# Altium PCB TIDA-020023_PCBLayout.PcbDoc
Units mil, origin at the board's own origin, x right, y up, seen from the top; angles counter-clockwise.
Board outline 1062.99 x 787.4 mil, 2 copper layers (Top Layer, Bottom Layer), stack 62 mil thick; 38 components, 20 nets, 86 pads, 14 vias.
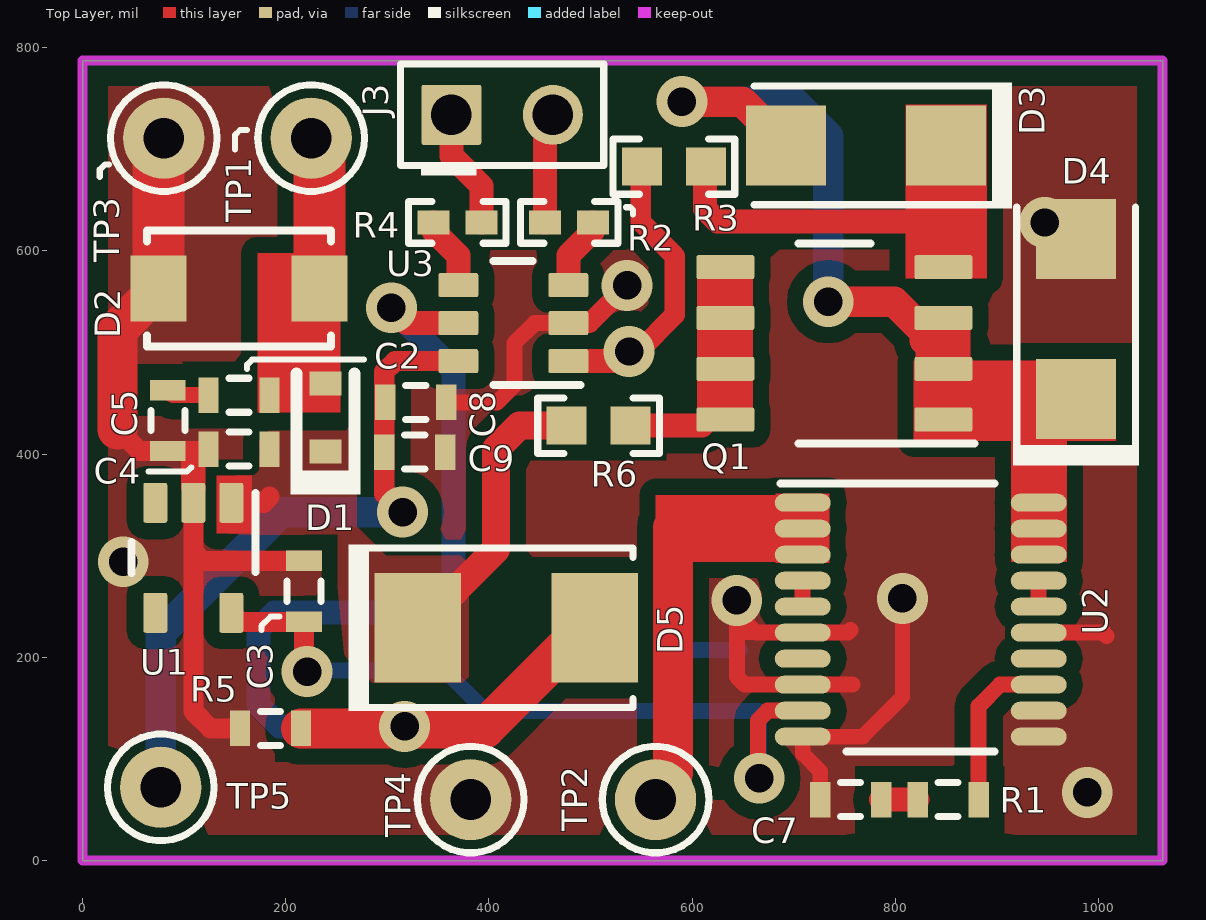
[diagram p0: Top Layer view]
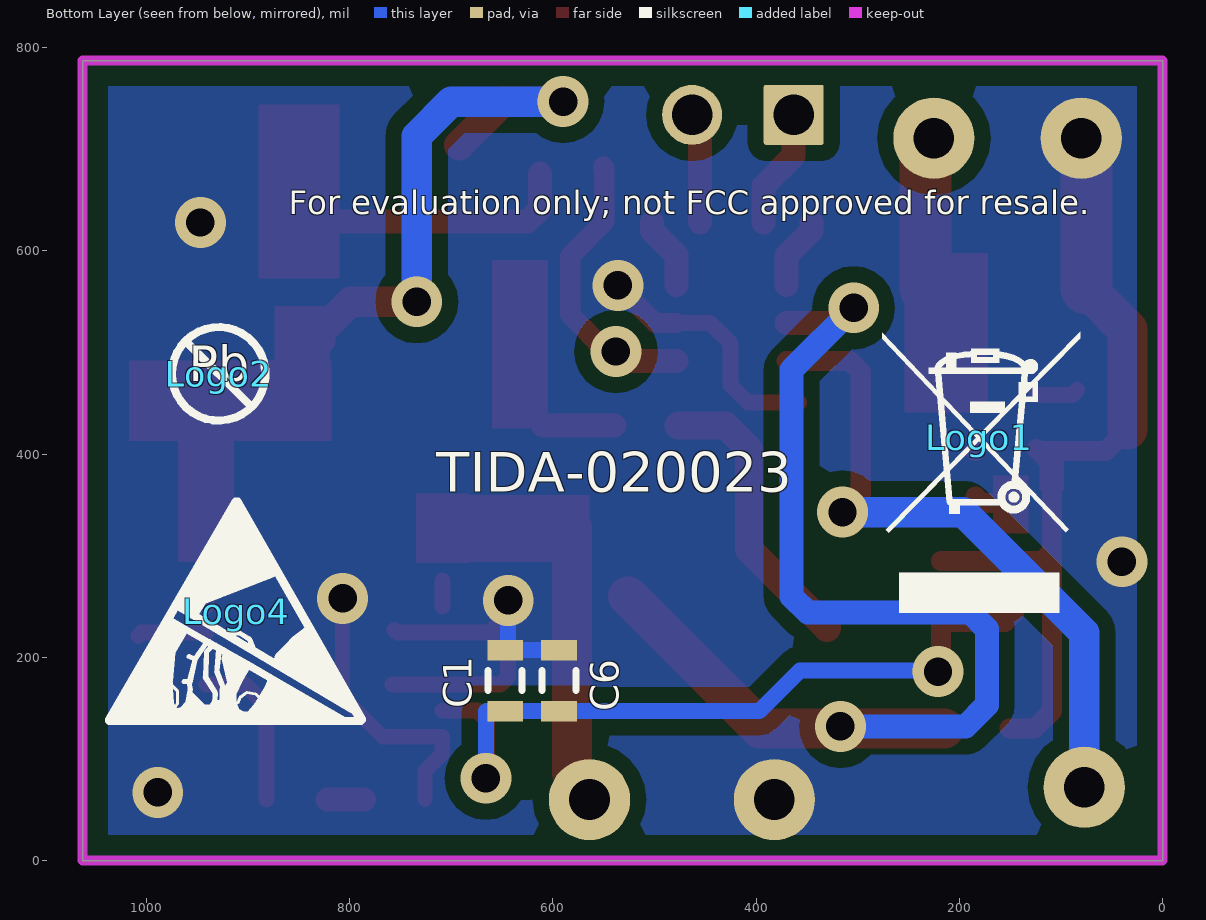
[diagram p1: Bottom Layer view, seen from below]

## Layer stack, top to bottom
Top Solder: solder mask 0.4, Solder Resist, Dk 3.5
Top Layer: signal copper 1.4
Dielectric1: core 59.2, FR-4, Dk 4.8
Bottom Layer: signal copper 1.4
Bottom Solder: solder mask 0.4, Solder Resist, Dk 3.5

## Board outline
0,0 1062.99,0 1062.99,787.4 0,787.4

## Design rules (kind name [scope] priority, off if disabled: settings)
AcuteAngle [All] p1: minimum=4.50000000000000E+0001 checktracksonly=FALSE
AssemblyTestPointUsage [All] p1: valid=2
BoardOutlineClearance BoardOutlineClearance_MountingHoles [OnCopper and InComponentClass('Mounting Holes')] p1: gap=40 ignorepadtopadclearanceinfootprint=FALSE
BoardOutlineClearance BoardOutlineClearance_Poly [OnCopper and IsPoly] p2: gap=25 ignorepadtopadclearanceinfootprint=FALSE
BoardOutlineClearance [OnCopper and Not InComponentClass('Logo') and not InComponentClass('FiducialMark') and not InRegion(1000,500,4000,800) and not InPoly] p3: gap=0 ignorepadtopadclearanceinfootprint=FALSE
Clearance Clearance_Keepouts [((IsTrack Or IsArc) And Not InPoly) And IsFree and IsKeepOut vs ((IsTrack Or IsArc) And Not InPoly) And IsFree and IsKeepOut] p1: gap=0 ignorepadtopadclearanceinfootprint=FALSE
Clearance Clearance_Poly [InPolygon] p2: gap=15.75 ignorepadtopadclearanceinfootprint=FALSE except(0: Arc-Hole Track-Hole SMDPad-Hole THPad-Hole Via-Hole Fill-Hole Poly-Hole Region-Hole Text-Hole)
Clearance [All] p3: gap=7.87 ignorepadtopadclearanceinfootprint=FALSE except(0: Arc-Hole Track-Hole SMDPad-Hole THPad-Hole Via-Hole Fill-Hole Poly-Hole Region-Hole Text-Hole)
ComponentClearance ComponentClearance_MountingHoles_FiducialMarks [InComponentClass('Mounting Holes') vs InComponentClass('FiducialMark')] p1: gap=50 collisioncheckmode=3 verticalgap=10 showdistances=FALSE
ComponentClearance ComponentClearance_Shunt [InComponentClass('Header') vs InComponentClass('Shunt')] p2: gap=0 collisioncheckmode=3 verticalgap=0 showdistances=FALSE
ComponentClearance ComponentClearance_Logo [InComponentClass('Logo')] p3: gap=0 collisioncheckmode=3 verticalgap=10 showdistances=FALSE
ComponentClearance ComponentClearance_ScrewToNut [(HasFootprint('NY PMS 440 0025 PH')) vs (HasFootprint('Keystone_1902C'))] p4: gap=5 collisioncheckmode=3 verticalgap=0 showdistances=FALSE
ComponentClearance ComponentClearance_MountingHoles [InComponentClass('Mounting Holes')] p5: gap=0 collisioncheckmode=3 verticalgap=100000 showdistances=FALSE
ComponentClearance ComponentClearance_SmallPassives [HasFootprint('0201*') or HasFootprint('0402*') or HasFootprint('0508') or HasFootprint('0603*') or HasFootprint('0612') or HasFootprint('0805*') or HasFootprint('0815*') or HasFootprint('0830*') or HasFootprint('1206*') or HasFootprint('1210*') or HasFootprint('1808*') or HasFootprint('1812*') or HasFootprint('1825*') or HasFootprint('2010*') or HasFootprint('2220*') or HasFootprint('2225*') or HasFootprint('2512*') or HasFootprint('2728*') or HasFootprint('3518*') vs HasFootprint('0201*') or HasFootprint('0402*') or HasFootprint('0508') or HasFootprint('0603*') or HasFootprint('0612') or HasFootprint('0805*') or HasFootprint('0815*') or HasFootprint('0830*') or HasFootprint('1206*') or HasFootprint('1210*') or HasFootprint('1808*') or HasFootprint('1812*') or HasFootprint('1825*') or HasFootprint('2010*') or HasFootprint('2220*') or HasFootprint('2225*') or HasFootprint('2512*') or HasFootprint('2728*') or HasFootprint('3518*')] p6: gap=0 collisioncheckmode=3 verticalgap=0 showdistances=FALSE
ComponentClearance ComponentClearance_THtoSMT [IsThruComponent vs IsSMTComponent] p7: gap=0 collisioncheckmode=3 verticalgap=0 showdistances=FALSE
ComponentClearance ComponentClearance_THtoTH [IsThruComponent vs IsThruComponent] p8: gap=0 collisioncheckmode=3 verticalgap=0 showdistances=FALSE
ComponentClearance [All] p9: gap=0 collisioncheckmode=3 verticalgap=0 showdistances=FALSE
DiffPairsRouting [All] p1: maxlimit=100 minlimit=10 mostfreqgap=10 toplayer_minwidth=15 toplayer_maxwidth=15 toplayer_prefwidth=15 bottomlayer_minwidth=15 bottomlayer_maxwidth=15 bottomlayer_prefwidth=15 maxuncoupledlength=1000
FabricationTestPointUsage TestPointUsage [All] p1: valid=2 allowmultiple=FALSE
FabricationTestpoint Testpoint [All] p1: side=3 testpointundercomponent=TRUE minsize=40 maxsize=100 preferedsize=60 minholesize=0 maxholesize=40 preferedholesize=32 testpointgrid=1 allowsidetop=TRUE allowsidebottom=TRUE usegrid=TRUE gridtolerance=0.01
FanoutControl Fanout_LCC [IsLCC] p1: bgadir=Out bgaviamode=Centered fanoutstyle=Auto fanoutdirection=Alternating viagrid=1 // Fanout_LCC (Default Rule)
FanoutControl Fanout_BGA [IsBGA] p2: bgadir=Out bgaviamode=Centered fanoutstyle=Auto fanoutdirection=Alternating viagrid=1 // Fanout_BGA (Default Rule)
FanoutControl Fanout_Default [All] p4: bgadir=Out bgaviamode=Centered fanoutstyle=Auto fanoutdirection=Alternating viagrid=1 // Fanout_Default (Default Rule)
FanoutControl Fanout_Small [(CompPinCount < 5)] p5: bgadir=Out bgaviamode=Centered fanoutstyle=Auto fanoutdirection=OutThenIn viagrid=1 // Fanout_Small (Default Rule)
HoleSize [All] p1: absolutevalues=TRUE maxlimit=251 minlimit=7.87 maxpercent=80.000 minpercent=20.000
MinimumAnnularRing MinimumAnnularRing_ThermalPadVias [IsVia and InAnyComponent] p1: minimumring=0
MinimumAnnularRing [All] p2: minimumring=0
MinimumSolderMaskSliver MinimumSolderMaskSliver_Logo [InComponentClass('Logo') vs InComponentClass('Logo')] p1: minsoldermaskwidth=0.7
MinimumSolderMaskSliver [All] p2: minsoldermaskwidth=3.94
PlaneConnect [All] p1: planeconnectstyle=Relief reliefexpansion=10 reliefentries=4 reliefconductorwidth=10 reliefairgap=10
PolygonConnect [All] p1: connectstyle=Direct reliefconductorwidth=10 reliefentries=4 polygonreliefangle="90 Angle" airgapwidth=10
RoutingVias ThermalPadVias [IsVia and InAnyComponent] p1: holewidth=7.87 width=19.68 viastyle="Through Hole" minholewidth=7.87 minwidth=19.68 maxholewidth=12.99 maxwidth=23.62
RoutingVias [All] p2: holewidth=16 width=34 viastyle="Through Hole" minholewidth=7.87 minwidth=26 maxholewidth=40 maxwidth=65
SilkToBoardRegionClearance [Not ((IsComment or IsDesignator) And (Hide <> 'False')) and not InRegion(1000,500,4000,800)] p1:
SilkToSilkClearance SilkToSilkClearance_Pb-FreeLogo [(HasFootprint('Pb-Free_Overlay_Medium') OR HasFootprint('Pb-Free_Overlay_Small')) vs (HasFootprint('Pb-Free_Overlay_Medium') OR HasFootprint('Pb-Free_Overlay_Small'))] p1: silktosilkclearance=0
SilkToSilkClearance [All] p2: silktosilkclearance=0
SilkToSolderMaskClearance SilkToComponentPadClearance [(IsPad or IsFill or IsRegion) and InAnycomponent] p1: minsilkscreentomaskgap=0 clearancetoexposedcopper=TRUE
SilkToSolderMaskClearance "Silk to Solder Mask Opening" [All] p2: minsilkscreentomaskgap=0 clearancetoexposedcopper=FALSE
SolderMaskExpansion [All] p1: expansion=1.97
Width [All] p1: maxlimit=100 minlimit=6 preferedwidth=10 checkconnectedcopper=TRUE
15 further rules are at their usual default settings.

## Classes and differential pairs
component class Header: J3
component class TIDA-020023_Schematics: C1 C2 C3 C4 C5 C6 C7 C8 C9 D1 D2 D3 D4 D5 J3 J4 Q1 R1 R2 R3 R4 R5 R6 TP1 TP2 TP3 TP4 TP5 U1 U2 U3
component class AssemblyNote: ZZ1 ZZ2 ZZ3 ZZ4
component class TIDA-020023_EVM_Hardware: Logo1 Logo2 Logo3 Logo4 ZZ1 ZZ2 ZZ3 ZZ4

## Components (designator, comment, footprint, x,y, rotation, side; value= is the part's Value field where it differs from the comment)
C1 "0603YC104JAT2A" 0603S 647,177 r270 bottom value=0.1uF
C2 "GRM188R72A104KA35J" 0603S 154,458 r180 top value=0.1uF
C3 "GRM188Z71C225KE43" 0603S 218,265 r90 top value=2.2uF
C4 "CGA3E1X7R1V105K080AC" 0603S 154,405 r0 top value=1uF
C5 "GRM188R72A104KA35J" 0603S 84,433 r270 top value=0.1uF
C6 "CGA3E1X7R1V105K080AC" 0603S 594,177 r270 bottom value=1uF
C7 "0603YC104JAT2A" 0603S 756,60 r180 top value=0.1uF
C8 "0603YC104JAT2A" 0603S 328,451 r0 top value=0.1uF
C9 "CGA3E1X7R1V105K080AC" 0603S 327,402 r0 top value=1uF
D1 "CDBU00340" SOD-523F 239,436 r90 top value=45V
D2 "SM4T23CAY" SMA_Bi 154,563 r0 top value=20V
D3 "B120-13-F" SMA 771,704 r180 top value=20V
D4 "B120-13-F" SMA 978,533 r90 top value=20V
D5 "SMBJ5366B-TP" SMB 417,229 r0 top value=39V
J3 "PEC02SAAN" CONN_PEC02SAAN 413,734 r0 top
Logo1 "WEEE logo" WEEE_Minimum 180.48,416 r180 bottom
Logo2 "Pb-Free Symbol" Pb-Free_Overlay_Small 929,479 r180 bottom
Logo3 "FCC disclaimer" FCC_disclaimer 2350,3380 r0 top
Logo4 "ESD Susceptible" ESD_Overlay_Medium 911.61,244.97 r180 bottom
Q1 "SQ4850EY" SOIC-8 740,509 r180 top value=60V
R1 "FC0603E50R0BTBST1" 0603S 852,60 r180 top value=50
R2 "CRCW04020000Z0EDHP" 0402 479,628 r0 top value=0
R3 "CRCW0603130RFKEA" 0603 582,683 r0 top value=130
R4 "CRCW04020000Z0EDHP" 0402 369,628 r180 top value=0
R5 "CRCW060310K0JNEA" 0603S 185,130 r0 top value=10k
R6 "CRCW0603130RFKEA" 0603 508,428 r180 top value=130
TP1 "5001" Keystone5001 225,711 r0 top
TP2 "5001" Keystone5001 564,60 r90 top
TP3 "5001" Keystone5001 80,711 r90 top
TP4 "5001" Keystone5001 382,60 r90 top
TP5 "5001" Keystone5001 77,72 r90 top
U1 "TPS70950QDBVRQ1" DBV0005A_N 109,298 r270 top
U2 "INA253A1IPWR" PW0020A_N 825,237 r0 top
U3 "TLV1805QDBVRQ1" DBV0006A_N 424,529 r180 top
ZZ1 "This Assembly Note is for PCB labels only" AssemblyNoteLabel 170,1215 r0 top
ZZ2 "These assemblies are ESD sensitive, ESD precautions shall be observed." AssemblyNote 170,1106.11 r0 top
ZZ3 "These assemblies must be clean and free from flux and all contaminants. Use of no clean flux is not acceptable." AssemblyNote 170,1017.56 r0 top
ZZ4 "These assemblies must comply with workmanship standards IPC-A-610 Class 2, unless otherwise specified." AssemblyNote 170,929 r0 top

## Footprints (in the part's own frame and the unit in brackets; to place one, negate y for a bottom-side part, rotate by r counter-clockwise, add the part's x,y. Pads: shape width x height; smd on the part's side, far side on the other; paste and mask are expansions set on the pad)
0402 [mm] "0402 from SM-752 data"
  rect 0.8x0.6 smd: 1(-0.6,0) 2(0.6,0)
  silkscreen extent -1.22,-0.52 1.22,0.52, body extent -0.55,-0.3 0.55,0.3, height 0.6
0603 [mm] "0603 from SM-752 data"
  rect 1x0.95 smd: 1(-0.8,0) 2(0.8,0)
  silkscreen extent -1.52,-0.69 1.52,0.69, body extent -0.87,-0.47 0.87,0.47, height 1
0603S [mil]
  rect 20x35 smd: 1(-30,0) 2(30,0)
  silkscreen extent -10,-17 10,17, body extent -34,-19 34,19, height 39
AssemblyNote [mil] "Assembly Note"
AssemblyNoteLabel [mil] "Assembly Note for PCB Labels"
CONN_PEC02SAAN [mm] "SULLINS"
  rrect7% 1.5x1.5 hole 1.016: 1(-1.27,0)
  round 1.5 hole 1.016: 2(1.27,0)
  silkscreen extent -2.54,-1.52 2.54,1.27, body extent -2.54,-1.27 2.54,1.27, height 8.38
DBV0005A_N [mm] "SOT23, 5-Leads, Body 2.9x1.6mm, Pitch 0.95mm, Lead Span 2.8mm, IPC Medium Density"
  rrect17% 1x0.6 smd: 1(-1.375,0.95) 2(-1.375,0) 3(-1.375,-0.95) 4(1.375,-0.95) 5(1.375,0.95)
  silkscreen extent -1.63,-1.55 0.38,1.55, body extent -1.42,-1.46 1.42,1.46, height 1.09
DBV0006A_N [mm] "SOT23, 6-Leads, Body 2.9x1.6mm, Pitch 0.95mm, Lead Span 2.8mm, IPC Medium Density"
  rrect17% 1x0.6 smd: 1(-1.375,0.95) 2(-1.375,0) 3(-1.375,-0.95) 4(1.375,-0.95) 5(1.375,0) 6(1.375,0.95)
  silkscreen extent -1.68,-1.55 0.5,1.55, body extent -1.42,-1.46 1.42,1.46, height 1.12
ESD_Overlay_Medium [mil]
  silkscreen extent -127,-109 125,110
FCC_disclaimer [mil]
Keystone5001 [mil] "For Keystone 500x miniature loop terminals"
  round 80 hole 40: 1(0,0)
  silkscreen extent -52,-52 52,52, body extent -49,-49 49,49, height 182
Pb-Free_Overlay_Small [mil]
  silkscreen extent -46,-46 46,46
PW0020A_N [mm] "TSOP, 20-Leads, Body 6.5x4.4mm, Pitch 0.65mm, IPC Medium Density"
  oval 1.4x0.45 smd: 1(-2.95,2.925) 2(-2.95,2.275) 3(-2.95,1.625) 4(-2.95,0.975) 5(-2.95,0.325) 6(-2.95,-0.325) 7(-2.95,-0.975) 8(-2.95,-1.625) 9(-2.95,-2.275) 10(-2.95,-2.925) 11(2.95,-2.925) 12(2.95,-2.275) 13(2.95,-1.625) 14(2.95,-0.975) 15(2.95,-0.325) 16(2.95,0.325) 17(2.95,0.975) 18(2.95,1.625) 19(2.95,2.275) 20(2.95,2.925)
  silkscreen extent -3.5,-3.3 1.85,3.4, body extent -3.21,-3.25 3.21,3.25, height 1
SMA [mm] "Molded Diode, 2-Leads, Body 4.3x2.6mm, IPC Medium Density, based on OnSemi component dimensions and land pattern"
  rect 2x2 smd: 1(-2,0) 2(2,0)
  silkscreen extent -3.66,-1.57 2.79,1.57, body extent -2.6,-1.3 2.6,1.3, height 2.42
SMA_Bi [mm] "SMD, 2-Leads, Body 4.275x2.575mm"
  rect 1.4x1.64 smd: 1(-2.015,0) 2(2.015,0)
  silkscreen extent -2.3,-1.45 2.3,1.45, body extent -2.52,-1.45 2.52,1.45, height 2.65
SMB [mil] "Molded Diode, 2-Leads, Body 5.4x3.6mm, IPC Medium Density, based on OnSemi component dimensions"
  rect 85x107.99 smd: 1(-87.01,0) 2(87.01,0)
  silkscreen extent -155,-82 125,82, body extent -106,-71 106,71, height 91
SOD-523F [mm] "COMCHIP"
  rect 0.6x0.8 smd paste-0.05: 1(-0.85,0) 2(0.85,0)
  silkscreen extent -1.92,-0.88 1.1,0.87, body extent -0.9,-0.5 0.9,0.5, height 0.85
SOIC-8 [mm] "duplicate of SO-8.  SOIC, 8-Leads, Body 5.0x4.0mm (max), Pitch 1.27mm, IPC Medium Density"
  rrect17% 1.45x0.6 smd: 1(-2.725,1.905) 2(-2.725,0.635) 3(-2.725,-0.635) 4(-2.725,-1.905) 5(2.725,-1.905) 6(2.725,-0.635) 7(2.725,0.635) 8(2.725,1.905)
  silkscreen extent -3.5,-2.5 0.9,2.5, body extent -3,-2.45 3,2.45, height 1.63
WEEE_Minimum [mil] "WEEElie bin"
  silkscreen extent -95,-172 99,104

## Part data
C1 C7 C8: "CAP, CERM, 0.1 µF, 16 V, +/- 5%, X7R, 0603", Cap_Case=0603, Manufacturer=AVX, Supplier Part Number 1=478-3726-1-ND, TempCo=X7R, Tolerance_%=5, Value1="0.039 ohm", Value2=16V, ValueDisplayed=0.1µF
C2 C5: "CAP, CERM, 0.1 µF, 100 V, +/- 10%, X7R, 0603", Cap_Case=0603, Manufacturer=MuRata, Supplier Part Number 1=490-6439-1-ND, TempCo=X7R, Tolerance_%=10, Value1=Unknown, Value2=100V, ValueDisplayed=0.1µF
C3: "CAP, CERM, 2.2 µF, 16 V, +/- 10%, X7R, 0603", Cap_Case=0603, Manufacturer=MuRata, Supplier Part Number 1=81-GRM188Z71C225KE3D, TempCo=X7R, Tolerance_%=10, Value1=Unknown, Value2=16V, ValueDisplayed=2.2µF
C4: "CAP, CERM, 1 µF, 35 V, +/- 10%, X7R, AEC-Q200 Grade 1, 0603", Cap_Case=0603, Manufacturer=TDK, Supplier Part Number 1=445-174215-1-ND, TempCo=X7R, Tolerance_%=10, Value1="0.005522 ohm", Value2=35V, ValueDisplayed=1µF
C6 C9: "CAP, CERM, 1 µF, 35 V, +/- 10%, X7R, AEC-Q200 Grade 1, 0603", Cap_Case=0603, Manufacturer=TDK, Supplier Part Number 1=445-174215-1-ND, TempCo=X7R, Tolerance_%=10, Value1="0.005522 ohm", Value2=35V, ValueDisplayed=22nf
D1: library part CMP-0081923-2, "Diode, Schottky, 45 V, 0.03 A, SOD-523F", Manufacturer="Comchip Technology", Value1=0.03A, Value2=0.37V
D2: library part CMP-0078854-3, "Diode, TVS, Bi, 20 V, 42.8 Vc, AEC-Q101, SMA (non-polarized)", Manufacturer=STMicroelectronics, Value1=400W
D3 D4: library part CMP-0028374-2, "Diode, Schottky, 20 V, 1 A, SMA", Manufacturer="Diodes Inc.", Value1=1A, Value2=0.5V
D5: library part CMP-0005659-4, "Diode, Zener, 39 V, 5 W, SMB", Manufacturer="Micro Commercial Components", Power_W=5W
J3: library part CMP-0002337-1, "Header, 100mil, 2x1, Tin, TH", Color=Black, Current_A=3A, Manufacturer="Sullins Connector Solutions", Supplier Part Number 1=S1012E-02-ND, Voltage_V=1.8kV
Logo1: library part CMP-0074769-1
Logo2: library part Pb-Free
Logo3: library part FCC_disclaimer, "FCC_disclaimer"
Logo4: library part ESD_Susceptible, "ESD Susceptible Symbol"
Q1: library part CMP-0000872-1, "MOSFET, N-CH, 60 V, 12 A, SOIC-8", Alternate Manufacturer=None, Manufacturer=Vishay-Siliconix, Supplier Part Number 1=SQ4850EY-T1-GE3-ND, Value1=0.03, Value2="20 nC"
R1: "RES, 50, 0.1%, 0.125 W, 0603", Manufacturer="Vishay Thin Film", Power_W=0.125, Supplier Part Number 1=FC0603-50BFCT-ND, TempCo="25 ppm/C", Tolerance_%=0.1, Value1=0.1%, Value2=0.125W, Value_Code=50R0, ValueDisplayed=50
R2 R4: library part CMP-0081856-1, "RES, 0, 0%, 0.2 W, AEC-Q200 Grade 0, 0402", Manufacturer=Vishay-Dale, Power_W=200mW, Supplier Part Number 1=541-0.0YBTR-ND, Tolerance_%=0%, Value2=0.2W, Value_Code=0
R3 R6: library part CMP-0022037-5, "RES, 130, 1%, 0.1 W, AEC-Q200 Grade 0, 0603", Manufacturer=Vishay-Dale, Power_W=100mW, Supplier Part Number 1=541-130HCT-ND, TempCo="100 ppm/C", Tolerance_%=1%, Value2=0.1W, Value_Code=130R, ValueDisplayed=130
R5: "RES, 10 k, 5%, 0.1 W, 0603", Manufacturer=Vishay-Dale, Power_W=0.1, Supplier Part Number 1=541-10KGCT-ND, TempCo="200 ppm/C", Tolerance_%=5, Value1=5%, Value2=0.1W, Value_Code=10k0, ValueDisplayed=10k
TP1 TP2 TP3 TP4 TP5: library part CMP-0055138-1, "Test Point, Miniature, Black, TH", Color=Black, Manufacturer=Keystone, Supplier Part Number 1=36-5001-ND
U1: library part CMP-0079136-1, "150-mA, 30-V, Ultra-Low IQ, Wide Input LDO with Reverse Current Protection for Automotive, DBV0005A (SOT-23-5)", Alternate Manufacturer="Texas Instruments"
U2: "Low- or High-Side, Bidirectional, Zero-Drift, Current-Shunt Monitor with Integrated Precision Low Inductive Shunt Resistor, PW0020A (TSSOP-20)", Alternate Manufacturer="Texas Instruments", Alternate PartNumber=INA253A1IPW
U3: library part CMP-0080758-2, "Automotive 40-V, microPower, Push-Pull Comparator with Shutdown, DBV0006A (SOT-23-6)", Alternate Manufacturer="Texas Instruments"
ZZ1: library part AssemblyNoteLabel
ZZ2 ZZ3 ZZ4: library part AssemblyNote

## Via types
v1: diameter 50, hole 28, Top Layer to Bottom Layer, 14 vias

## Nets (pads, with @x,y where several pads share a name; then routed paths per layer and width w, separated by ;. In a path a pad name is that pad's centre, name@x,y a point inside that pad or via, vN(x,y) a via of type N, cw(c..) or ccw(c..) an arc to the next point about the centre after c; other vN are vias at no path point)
5V: C1.2 C3.1 C6.2 U1.5 U2.9 | length 770.8
  Top Layer w15.75: v1@665,84 665,138 674.43,147.43 U2.9
  Top Layer w19.68: U1.5 155.26,235 C3.1 218,196 231,196 v1(221,186)
  Bottom Layer w15.75: v1(221,186) 222,187 357,187 397,147 C6.2 C1.2 665.43,147 666,146.43 v1(666,81)
12V: C2.1 D1.2 D2.2 TP1.1 | length 151.4
  Top Layer w51.18: TP1.1 233.33,702.67 D2.2
24V: C8.1 C9.1 TP5.1 U3.6 | length 662
  Top Layer w20: v1(315,343) 297,361 297,481 307.6,491.6 U3.6
  Bottom Layer w30: TP5.1 77,224 196,343 v1(315,343)
GND: C1.1 C3.2 C4.1 C5.2 C6.1 C7.2 C8.2 C9.2 D2.1 D4.2 R5.1 TP3.1 TP4.1 U1.2 U2.6 U2.8 U2.10 U2.11 U2.12 U2.15 U3.2 | length 1837.6
  Top Layer w15: C7.2 726,88 708.86,105.14 U2.10 767.84,121.84 807,161 v1(807,258)
  Top Layer w15.75: C8.2 408,451 425,468 425,509 445,529 U3.2 ; v1(644,256) v1@644,243 ; 756,227 753.2,224.2 U2.6 662.8,224.2 v1@644,243 ; 757.98,173.02 U2.8 651.98,173.02 644,181 v1@644,243 ; U2.15 1004.8,224.2 1008,221
  Top Layer w19.68: 34.56,424.44 56,403 C5.2 C4.1@122,403 ; C4.1 C4.1@122,403 ; R5.1@150.57,130 126,130 109,147 109,304 ; C3.2 118,295 109,304 ; U3.2 499,529 v1(536,566) ; 109,304 U1.2 109,390 C4.1@122,403
  Top Layer w39.37: 34.56,424.44 34.56,522.9 D2.1
  Top Layer w51.18: D2.1 74.67,705.67 TP3.1
  Bottom Layer w15.75: C6.1 C1.1 ; C1.1@644,210 v1(644,256)
  other v1: 989,67 40,294 947,628
INAOUTTOMCU2.4: C7.1 R1.2 | length 36
  Top Layer w23.62: C7.1 R1.2
NetC2_2: C2.2 C5.1 | length 42.1
  Top Layer w15.75: C5.1 89,458 C2.2
NetD3_1: D3.1 Q1.4 R3.2 | length 255.2
  Top Layer w23.62: R3.2@612.5,676 612.5,641.5 625,629 828,629
NetJ3_1: J3.1 R4.1 | length 118.3
  Top Layer w23.62: J3.1 363,693.62 392.62,664 R4.1
NetJ3_2: J3.2 R2.1 | length 135.7
  Top Layer w23.62: R2.1 455.38,726.38 J3.2 463,723 J3.2@474,734
NetQ1_5: Q1.5 Q1.6 Q1.7 Q1.8 R6.1 | length 70.2
  Top Layer w23.62: R6.1 Q1.8@609.72,428
NetR1_1: R1.1 U2.13 | length 159.9
  Top Layer w15.75: R1.1 882,152 903.02,173.02 U2.13
NetR2_2: R2.2 U3.3 | length 71.7
  Top Layer w23.62: U3.3 478.13,595.36 502.62,619.85 R2.2
NetR3_1: R3.1 U3.1 | length 284
  Top Layer w20: v1(538,501) 547,501 583,537 583,595 549.5,628.5 549.5,682 R3.1
  Top Layer w23.62: U3.1 528.6,491.6 v1(538,501)
NetR4_2: R4.2 U3.4 | length 71.7
  Top Layer w23.62: R4.2 345.38,619.85 369.87,595.36 U3.4
NetU2_4: U2.4 U2.5 | length 25.6
  Top Layer w15.75: U2.5 U2.4
NetU2_16: U2.16 U2.17 | length 25.6
  Top Layer w15.75: U2.16 U2.17
OUT_SWITCH: D3.2 D4.1 Q1.1 Q1.2 Q1.3 U2.18 U2.19 U2.20 | length 556.6
  Top Layer w30: v1(590,747) 649.26,747 D3.2 ; v1(734,550) 799,550 829,520 829,512
  Bottom Layer w30: v1(590,747) 700,747 734,713 v1(734,550)
Shutdown: D5.2 R5.2 U3.5 | length 1179.1
  Top Layer w23.62: v1(304,544) 319,529 U3.5
  Top Layer w39.37: R5.2 396.01,130 D5.2@526,259.99
  Bottom Layer w23.62: v1(304,544) 365,483 365,260 349,244 189,244 173,228 173,153 194,132 v1(317,132)
SOLENOID_1: TP2.1 U2.1 U2.2 U2.3 | length 266
  Top Layer w39.37: TP2.1@564,69 581,86 581,328
VCC_12V: C4.2 D1.1 D5.1 R6.2 U1.1 | length 328.9
  Top Layer w19.68: U1.1 178,352.14 184,358.14 ; C4.2@184,403.1 C4.2
  Top Layer w27.56: D5.1 407,306.01 407,405 430,428 R6.2
pads on no net: U1.3 U1.4 U2.7 U2.14

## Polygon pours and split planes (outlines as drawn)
GND on Top Layer "TOP_LAYER_GND_P010" (solid, remove dead copper, pour order 10): 0,785 -1,784 -1,0 1063,0 1065,2 1065,786
VCC_12V on Top Layer "TOP_LAYER_VCC_12V_P002" (solid, remove dead copper, pour order 2): 374,175 380,181 380,295 375,300 299,300 270,329 270,390 321,441 321,444 318,447 283,447 259,423 176,423 174,421 174,384 169,379 136,379 132,375 132,330 140,322 232,317 248,300 258,202 285,175
GND on Bottom Layer "BOTTOM_LAYER_GND_P012" (solid, remove dead copper, pour order 12): -4,791 1057,791 1066,782 1066,-2 1,-2 -4,3

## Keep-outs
Keep-Out Layer:
  the board outline again, w10
  text ".Layer_Name" at 577,-858.49 h60

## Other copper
Top Layer:
  rectangle net 12V: 172,441 254,598
  rectangle net NetQ1_5: 605,425 660,591
  rectangle net NetD3_1: 810,573 890,744
  rectangle net GND: 642,217 681,230
  rectangle net SOLENOID_1: 564,294 724,360
  rectangle net SOLENOID_1: 682,293 735,361
  rectangle net OUT_SWITCH: 914,294 969,415
  rectangle net OUT_SWITCH: 818,413 1017,492
  rectangle net OUT_SWITCH: 820,424 874,546
  rectangle net VCC_12V: 132,322 167,379
  rectangle net GND: 97,364 121,394
  text "Top Layer" at 577,-858.49 h60
Bottom Layer:
  text "Bottom Layer" at 577,-858.49 h60

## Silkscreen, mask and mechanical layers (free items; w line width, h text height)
Top Overlay:
  lines w6: 17,673 17,680 22,685 26,685 ; 65,383 103,383 107,387 ; 150,700 150,714 155,719 162,719 ; 162,484 162,488 167,493 173,493 190,493 277,493 ; 176,227 176,231 185,240 194,240 ; 535,643 539,643 542,640 542,636
  text ".Layer_Name" at 577,-858.49 h60
Bottom Overlay:
  text "TIDA-020023" at 715,350 h66.93
  text ".Layer_Name" at 577,-858.49 h60
Top Paste:
  text ".Layer_Name" at 577,-858.49 h60
Bottom Paste:
  text ".Layer_Name" at 577,-858.49 h60
Top Solder:
  text ".Layer_Name" at 577,-858.49 h60
  text ".Layer_Name" at 577,-858.49 h60
Bottom Solder:
  text ".Layer_Name" at 577,-858.49 h60
Drill Guide:
  text ".Layer_Name" at 577,-858.49 h60
M1 Board Outline:
  the board outline again, w10
M2 Board Dimensions:
  rectangle: 125,-400 500,-275
  rectangle: 0,-275 125,-150
  lines w7: 0,-275 1000,-275 ; 125,-400 125,-150 ; 250,-400 250,-150 ; 500,-400 500,-150 ; 750,-400 750,-150 ; 0,-400 0,-150 1000,-150 1000,-400 0,-400
M3 3D STEP Top:
  text ".Layer_Name" at 577,-858.49 h60
M4 3D STEP Bottom:
  text ".Layer_Name" at 577,-858.49 h60
M5 Assembly Top:
  circle w6: c146,315 r6.76
  lines w10: -292,-930.17 6308,-930.17 ; -292,-726.83 6310,-726.83 ; -292,-523.5 -292,-1133.5 3713,-1133.5 6310,-1133.5 6310,-523.5 -291.5,-523.5 -291.5,-1133.5 1284,-1133.5 ; 2173,-1133.5 2173,-523.5 ; 3440,-726.83 3440,-523.5 ; 4280,-726.83 4280,-523.5 ; 4902,-1140 4902,-937.17
  text "COMPONENTS MARKED 'DNP' SHOULD NOT BE POPULATED." at 1153.5,-318.5 h20
  text "ASSEMBLY VARIANT:" at 1153,-434 h20
  text ".VariantName" at 2189,-434 h20
  text ".PCB_Rev" at 3720,-647 h20
  text ".PRJ_Number" at 2721,-649 h20
  text "REV:" at 3478,-651 h20
  text "BOARD #:" at 2217,-654 h20
  text "PCB VIEWED FROM TOP SIDE" at -228.5,-655.67 h20
  text "SVN REV:" at 4330,-661.67 h20
  text ".VersionControl_RevNumber" at 4836,-661.67 h20
  text "M5 Assembly Top" at 1052,-856 h20
  text "TID #:" at 2248,-859 h20
  text ".TID" at 2793.5,-859 h20
  text "PLOT NAME =" at -228.5,-1064.34 h20
  text ".plot_File_Name" at 577,-1064.34 h20
  text "GENERATED    :" at 2250,-1064.34 h20
  text ".Print_Date" at 3119.5,-1064.34 h20
  text ".Print_Time" at 3848.5,-1064.34 h20
  text "TEXAS INSTRUMENTS" at 5113,-1064.34 h20
M6 Assembly Bottom:
  lines w10: -292.5,-727.33 6309.5,-727.33 ; -290.5,-930.67 6309.5,-930.67 ; 1115.5,-1140.5 1115.5,-937.67 ; 1737.5,-727.33 1737.5,-524 ; 2577.5,-727.33 2577.5,-524 ; 3844.5,-1134 3844.5,-524 ; 4733.5,-1134 6309,-1134 6309,-524 -292.5,-524 -292.5,-1134 2304.5,-1134 6309.5,-1134 6309.5,-524
  text "COMPONENTS MARKED 'DNP' SHOULD NOT BE POPULATED." at 6102,-318 h60
  text ".VariantName" at 5058,-434 h60
  text "ASSEMBLY VARIANT:" at 6097,-434 h60
  text ".VersionControl_RevNumber" at 1182,-655 h60
  text "SVN REV:" at 1688,-655 h60
  text ".PCB_Rev" at 2232.5,-656 h60
  text "REV:" at 2524,-656 h60
  text ".PRJ_Number" at 3224,-656.17 h60
  text "BOARD #:" at 3769.5,-656.17 h60
  text "PCB VIEWED FROM BOTTOM SIDE" at 6246,-656.17 h60
  text "M6 Assembly Bottom" at 6252,-858 h60
  text ".TID" at 3224,-859.5 h60
  text "TID #:" at 3769.5,-859.5 h60
  text "TEXAS INSTRUMENTS" at 904.5,-1064.84 h60
  text ".Print_Time" at 2169,-1064.84 h60
  text ".Print_Date" at 2898,-1064.84 h60
  text "GENERATED    :" at 3767.5,-1064.84 h60
  text ".plot_File_Name" at 5440.5,-1064.84 h60
  text "PLOT NAME =" at 6246,-1064.84 h60
M9 Title Sheet:
  drawing of 57 lines, arcs and shapes, not listed
  text "1" at 739.84,8036.5 h70
  text "2" at 3235.5,8036.5 h70
  text "3" at 5724.84,8036.5 h70
  text "4" at 8231.51,8036.5 h70
  text "5" at 10730.5,8036.5 h70
  text "6" at 13235.5,8036.5 h70
  text "A" at -416.5,6893.5 h70
  text "A" at 14383.5,6893.5 h70
  text "B" at -416.5,4513.5 h70
  text "B" at 14383.5,4513.5 h70
  text "C" at -416.5,2138.5 h70
  text "C" at 14383.5,2138.5 h70
  text "PROJECT TITLE:" at 11343.5,277.5 h45
  text ".PRJ_Title" at 11393.5,144.17 h70
  text "DESIGNED FOR:" at 11343.5,-23.5 h45
  text ".PRJ_Customer" at 11393.5,-163.5 h70
  text "D" at -416.5,-231.5 h70
  text "D" at 14383.5,-231.5 h70
  text "FILE NAME:" at 11343.5,-323.5 h45
  text ".PCB_File_Name_No_Path" at 11393.5,-443.5 h70
  text "Texas Instruments (TI) and/or its licensors do not warrant the accuracy or completeness of this specification" at 6374,-605.34 h45
  text "ENGINEER:" at 11343.5,-613.5 h45
  text "LAYOUT BY:" at 12848.5,-613.5 h45
  text "or any information contained therein. TI and/or its licensors do not warrant that this design will meet" at 6329.01,-718 h45
  text ".PRJ_Engineer" at 11393.5,-768.49 h70
  text ".PCB_Layout" at 12899,-768.49 h70
  text "the specifications, will be suitable for your application or fit for any particular purpose, or will operate in" at 6329.01,-830.67 h45
  text "ALTIUM DESIGNER VERSION:" at 12848.5,-923.5 h45
  text "an implementation. TI and/or its licensors do not warrant that the design is production worthy. You should" at 6329.01,-943.33 h45
  text "completely validate and test your design implementation to confirm the system functionality for your application." at 6374,-1056 h45
  text ".print_Scale" at 11393.5,-1056.83 h70
  text ".Application_BuildNumber" at 12899,-1056.83 h70
  text "1" at 739.84,-1263.5 h70
  text "2" at 3235.5,-1263.5 h70
  text "3" at 5724.84,-1263.5 h70
  text "4" at 8231.51,-1263.5 h70
  text "5" at 10730.5,-1263.5 h70
  text "6" at 13235.5,-1263.5 h70
M10 Fab Notes:
  drawing of 173 lines, arcs and shapes, not listed
  text "THIS IS NOT AN IMPEDANCE CONTROL BOARD." at 11293,6466 h60
  text "ALL VIAS ARE NON _TENTED." at 11297,6369 h60
  text "DESIGN INFORMATION" at 12378.02,6201 h60
  text "MIN. TRACK WIDTH:" at 11733.46,6021 h60
  text "15" at 12829.7,6021 h60
  text "MIL" at 12984.46,6021 h60
  text "MIN. CLEARANCE:" at 11733.46,5889 h60
  text "0.2" at 12769.7,5889 h60
  text "mm" at 12984.46,5889 h60
  text "MIN. VIA PAD SIZE:" at 11733.46,5757 h60
  text "24" at 12799.71,5757 h60
  text "MIL" at 12984.46,5757 h60
  text "0.05mm (2MIL)" at 12428.46,5615.29 h60
  text "MINIMUM ANNULAR RING" at 11404.23,5611 h60
  text "EXTERNAL" at 13136.46,5611 h60
  text "PER" at 11604.23,5493 h60
  text "IPC-D-275 CLASS 2 LEVEL C" at 11824.23,5493 h60
  text "MIL, HOLES" at 13312.46,5380.71 h60
  text "+/-" at 12920,5380 h60
  text "+/-" at 13774,5380 h60
  text "REGISTRATION TOLERANCES:" at 11404.23,5375 h60
  text "METAL" at 12604,5375 h60
  text "5" at 13180.2,5375 h60
  text "3" at 14013.2,5375 h60
  text "MIL" at 14129.46,5375 h60
  text "+/-" at 13774,5262 h60
  text "HOLE SIZE TOLERANCE (UNLESS OTHERWISE SPECIFIED):" at 11404.23,5257 h60
  text "3" at 14013.2,5257 h60
  text "MIL" at 14129.46,5257 h60
  text "MATERIAL:" at 11329.46,5047.54 h60
  text "FR-4 High Tg" at 12315.9,4907.21 h60
  text "FR-408" at 11750.46,4898.64 h60
  text "OTHER" at 13238.46,4898.64 h60
  text "X" at 12161,4895 h60
  text "62 MIL (1.6mm) +/-10%" at 12070.56,4735.92 h60
  text "THICKNESS:" at 11404.23,4731.64 h60
  text "X" at 11942.4,4731.64 h60
  text "OTHER" at 13355.46,4731.64 h60
  text "TOLERANCE:" at 11404.23,4573.64 h60
  text "X" at 12243.53,4573.64 h60
  text "ANSI IPC-6012 TYPE 3 CLASS 2" at 12430.48,4573.64 h60
  text "OTHER +/-" at 12430.46,4417.64 h60
  text "BOW & TWIST:" at 11404.23,4260.64 h60
  text "X" at 12243.53,4260.64 h60
  text "ANSI IPC-6012 TYPE 3 CLASS 2" at 12430.48,4260.64 h60
  text "OTHER +/-" at 12430.46,4102.13 h60
  text "DRILLING:" at 11329.46,3963.64 h60
  text "REFERENCE:" at 11404.23,3846.64 h60
  text "X" at 12052.46,3846.64 h60
  text "AS SHOWN" at 12239.46,3846.64 h60
  text "X" at 12953.46,3846.64 h60
  text "NC_DRILL FILES" at 13090.46,3846.64 h60
  text "PTH COPPER THICKNESS:" at 11404.23,3688.64 h60
  text "X" at 12534.46,3688.64 h60
  text "20-30 um" at 12671.46,3688.64 h60
  text "OTHER" at 13388.46,3688.64 h60
  text "BOARD FINISH:" at 11329.46,3529.64 h60
  text "SILKSCREEN:" at 11484.68,3411.64 h60
  text "X" at 12433.46,3411.64 h60
  text "TOP" at 12559.46,3411.64 h60
  text "X" at 12943.46,3411.64 h60
  text "BOTTOM" at 13070.46,3411.64 h60
  text "SILKSCREEN COLOR:" at 11484.68,3244.64 h60
  text "X" at 12432.42,3244.64 h60
  text "WHITE" at 12559.46,3244.64 h60
  text "OTHER" at 13070.46,3244.64 h60
  text "X" at 12563.42,3085.44 h60
  text "GREEN" at 12690.46,3085.44 h60
  text "OTHER" at 13308.46,3085.44 h60
  text "SOLDER RESIST COLOR:" at 11484.68,3074.64 h60
  text "X" at 12563.42,2915.44 h60
  text "MATTE" at 12690.46,2915.44 h60
  text "SEMI-GLOSS" at 13308,2914.8 h60
  text "IMMERSION GOLD (ENIG)" at 12390.46,2726.92 h60
  text "ENEPIG" at 13728,2723.64 h60
  text "SURFACE FINISH:" at 11329.46,2722.64 h60
  text "X" at 12203.51,2722.64 h60
  text "IMM. TIN/SILVER OR EQUIV" at 11659,2565.64 h60
  text "OTHER" at 13090.46,2565.64 h60
  text "ARRAY/PANEL:" at 11329.46,2386.64 h60
  text "CUT AND TRIM PER M1 BOARD OUTLINE" at 12390.46,2382.35 h60
  text "N.C. ROUTE" at 12390.46,2230.64 h60
  text "X" at 13069.46,2230.64 h60
  text "V. SCORE" at 13256.46,2230.64 h60
  text "CERTIFICATION:" at 11329.46,2093.64 h60
  text "MATERIALS AND WORKMANSHIP FOR ALL PCBS" at 12054.46,2093.64 h60
  text "TO MEET OR EXCEED THE REQUIREMENTS OF:" at 12054.46,1995.64 h60
  text "X" at 11680.96,1859.13 h60
  text "ANSI IPC-A-600F CLASS ->" at 11819.96,1859.13 h60
  text "X" at 13459.02,1859.13 h60
  text "2" at 13577.96,1859.14 h60
  text "1" at 13262.96,1857.64 h60
  text "3" at 13931.96,1857.64 h60
  text "X" at 12495.02,1699.64 h60
  text "RoHS" at 12631.96,1699.64 h60
  text "OTHER" at 13276.36,1699.64 h60
  text "PER ORDER" at 13673.42,1699.64 h60
  text "ALL BOARDS MUST MEET OR EXCEED UL94-V0 REQUIREMENTS." at 11357,1534 h60
  text "PCB MUST BEAR THE UL94V-0 UL REGISTERED MATERIAL ID NUMBER" at 11357,1414 h60
  text "ADDITIONAL REQUIREMENTS:" at 11329.46,1240.64 h60
  text "MICROSECTION:" at 11404.23,1125.64 h60
  text "YES" at 12309.96,1125.64 h60
  text "REQUIRED" at 13171.46,969.49 h60
  text "BARE BOARD ELEC. TEST:" at 11404.23,966.64 h60
  text "NONE" at 12709.96,966.64 h60
  text "X" at 13044.46,966.64 h60
  text "PER ORDER" at 13763.46,966.64 h60
M11 Gerber Information:
  lines w10: -292,-930.17 6308,-930.17 ; -292,-726.83 6310,-726.83 ; -292,-523.5 -292,-1133.5 3713,-1133.5 6310,-1133.5 6310,-523.5 -291.5,-523.5 -291.5,-1133.5 1284,-1133.5 ; 2173,-1133.5 2173,-523.5 ; 3440,-726.83 3440,-523.5 ; 4280,-726.83 4280,-523.5 ; 4902,-1140 4902,-937.17
  text "ALL ARTWORK VIEWED FROM TOP SIDE" at -228.5,-655.67 h60
  text "BOARD #:" at 2248,-655.67 h60
  text ".PRJ_Number" at 2793.5,-655.67 h60
  text "REV:" at 3638,-655.67 h60
  text ".PCB_Rev" at 3929.5,-655.67 h60
  text "SVN REV:" at 4476,-655.67 h60
  text ".VersionControl_RevNumber" at 4982,-655.67 h60
  text "LAYER NAME =" at -228.5,-858.49 h60
  text "TID #:" at 2248,-859 h60
  text ".TID" at 2793.5,-859 h60
  text "PLOT NAME =" at -228.5,-1064.34 h60
  text ".plot_File_Name" at 577,-1064.34 h60
  text "GENERATED    :" at 2250,-1064.34 h60
  text ".Print_Date" at 3119.5,-1064.34 h60
  text ".Print_Time" at 3848.5,-1064.34 h60
  text "TEXAS INSTRUMENTS" at 5113,-1064.34 h60
M12 Stackup:
  drawing of 191 lines, arcs and shapes, not listed
  text "Layer" at 6617.5,6134.5 h60
  text "Name" at 7027.41,6134.5 h60
  text "Material" at 7957.16,6134.5 h60
  text "Thickness" at 8816.92,6134.5 h60
  text "Constant" at 9466.76,6134.5 h60
  text "Board Layer Stack" at 10036.62,6134.5 h60
  text "1" at 6617.5,6014.5 h60
  text "Top Overlay" at 7027.41,6014.5 h60
  text "2" at 6617.5,5894.5 h60
  text "Top Solder" at 7027.41,5894.5 h60
  text "Solder Resist" at 7957.16,5894.5 h60
  text "0.40mil" at 8816.92,5894.5 h60
  text "3.5" at 9466.76,5894.5 h60
  text "3" at 6617.5,5774.5 h60
  text "Top Layer" at 7027.41,5774.5 h60
  text "Copper" at 7957.16,5774.5 h60
  text "1.40mil" at 8816.92,5774.5 h60
  text "4" at 6617.5,5654.5 h60
  text "Dielectric1" at 7027.41,5654.5 h60
  text "FR-4" at 7957.16,5654.5 h60
  text "59.20mil" at 8816.92,5654.5 h60
  text "4.8" at 9466.76,5654.5 h60
  text "5" at 6617.5,5534.5 h60
  text "Bottom Layer" at 7027.41,5534.5 h60
  text "Copper" at 7957.16,5534.5 h60
  text "1.40mil" at 8816.92,5534.5 h60
  text "6" at 6617.5,5414.5 h60
  text "Bottom Solder" at 7027.41,5414.5 h60
  text "Solder Resist" at 7957.16,5414.5 h60
  text "0.40mil" at 8816.92,5414.5 h60
  text "3.5" at 9466.76,5414.5 h60
  text "7" at 6617.5,5294.5 h60
  text "Bottom Overlay" at 7027.41,5294.5 h60
M13 Component Bodies Top:
  text ".Layer_Name" at 577,-858.49 h60
M14 Component Bodies Bottom:
  text ".Layer_Name" at 577,-858.49 h60
M15 Courtyards Top:
  text ".Layer_Name" at 577,-858.49 h60
M16 Courtyards Bottom:
  text ".Layer_Name" at 577,-858.49 h60
Drill Drawing:
  circle w10: c6767.62,4591.83 r33.33
  lines w10: 6734.29,4408.5 6800.96,4408.5 6800.96,4475.17 6734.29,4475.17 6734.29,4408.5
  lines w15: 6674.5,4363.5 10119.6,4363.5 ; 6674.5,4663.5 10119.6,4663.5 ; 7225.38,4213.5 7225.38,4813.5 ; 7755.24,4213.5 7755.24,4813.5 ; 8834.93,4213.5 8834.93,4813.5 ; 9340.8,4213.5 9340.8,4813.5 ; 6674.5,4213.5 10119.6,4213.5 10119.6,4813.5 6674.5,4813.5 6674.5,4213.5
  text "Symbol" at 6764.5,4708.5 h72
  text "Count" at 7270.38,4708.5 h72
  text "Hole Size" at 7800.24,4708.5 h72
  text "Plated" at 8879.93,4708.5 h72
  text "Hole Type" at 9385.8,4708.5 h72
  text "14" at 7270.38,4558.5 h60
  text "28.00mil (0.711mm)" at 7800.24,4558.5 h60
  text "PTH" at 8879.93,4558.5 h60
  text "Round" at 9385.8,4558.5 h60
  text "7" at 7270.38,4408.5 h60
  text "40.00mil (1.016mm)" at 7800.24,4408.5 h60
  text "PTH" at 8879.93,4408.5 h60
  text "Round" at 9385.8,4408.5 h60
  text "21 Total" at 7270.38,4258.5 h60
  text "DRILL TOLERANCE:" at 7386,3995 h60
  text "FOR PTH +/- 3MIL" at 7386,3845 h60
  text "FOR NPTH +/- 2MIL" at 7386,3740 h60
  text ".Layer_Name" at 577,-858.49 h60
M17 Embedded Cavity:
  text ".Layer_Name" at 577,-858.49 h60
M18 Embedded Assembly:
  text ".Layer_Name" at 577,-858.49 h60
M19 Embedded Keepout:
  text ".Layer_Name" at 577,-858.49 h60

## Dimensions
0,0 to 1062.99,0 on M2 Board Dimensions
0,0 to 0,787.4 on M2 Board Dimensions
0,-400 to 1000,-400 on M2 Board Dimensions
